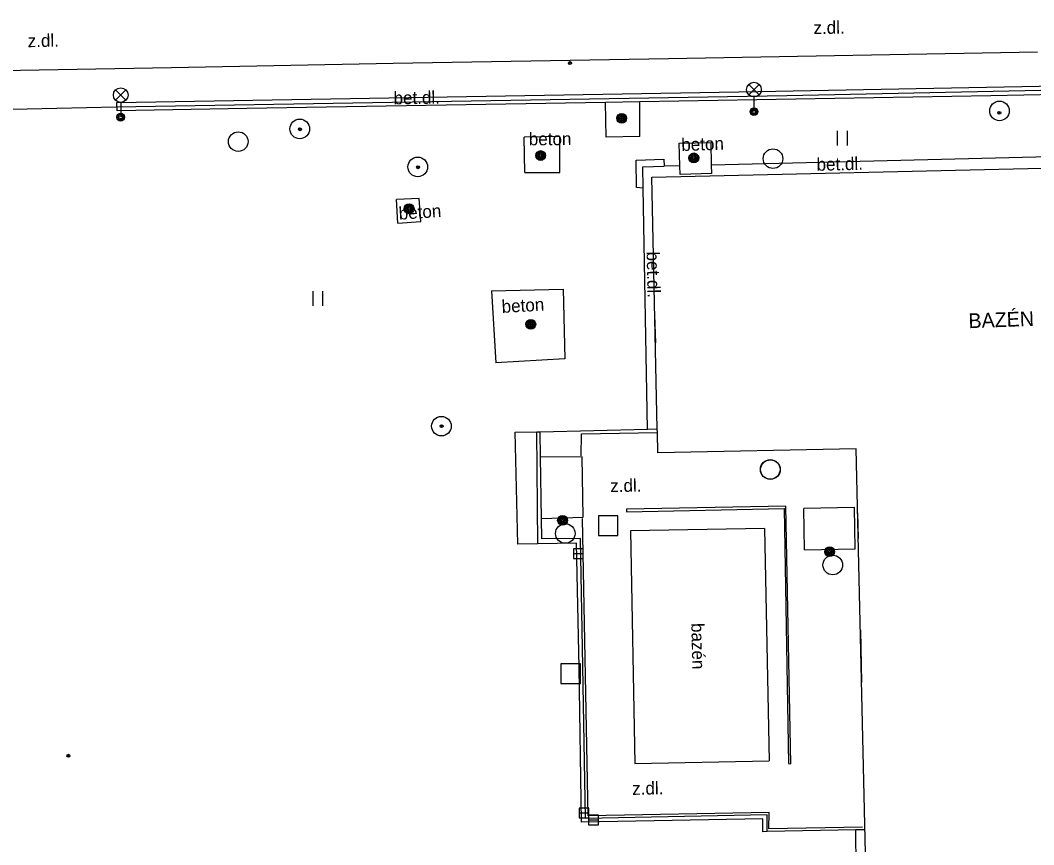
# Model space of a CAD drawing. Extents: x -641829 to -641525, y -1114855 to -1114359.
# Drawn here: x -641632.1 to -641580.3, y -1114713.1 to -1114671 of the extents above; entities that cross this region are included whole.
import ezdxf

# ---------------------------------------------------------------- set-up
doc = ezdxf.new("R2010")
doc.units = 0
for name, color, linetype in [('Vrstva 11', 7, 'Continuous'), ('Vrstva 20', 7, 'Continuous'), ('Vrstva 25', 7, 'Continuous'), ('Vrstva 26', 7, 'Continuous'), ('Vrstva 27', 7, 'Continuous'), ('Vrstva 33', 7, 'Continuous'), ('Vrstva 36', 7, 'Continuous'), ('Vrstva 40', 7, 'Continuous'), ('Vrstva 41', 7, 'Continuous'), ('Vrstva 5', 7, 'Continuous'), ('Vrstva 6', 7, 'Continuous'), ('Vrstva 7', 7, 'Continuous')]:
    doc.layers.add(name, color=color, linetype=linetype)

msp = doc.modelspace()

# ---------------------------------------------------------------- linework, layer by layer
at = {"layer": 'Vrstva 11'}
for p, q in [((-641613.03, -1114673.15), (-641598.98, -1114672.9)), ((-641598.98, -1114672.9), (-641580.14, -1114672.56)), ((-641633.01, -1114673.52), (-641624.34, -1114673.36)), ((-641624.34, -1114673.36), (-641613.03, -1114673.15)), ((-641594.4, -1114674.59), (-641569.41, -1114674.12)), ((-641561.56, -1114674.35), (-641582.52, -1114674.81)), ((-641627.12, -1114675.16), (-641594.4, -1114674.59)), ((-641627.11, -1114675.58), (-641627.12, -1114675.16)), ((-641620.5, -1114675.46), (-641627.11, -1114675.58)), ((-641602.16, -1114676.92), (-641602.19, -1114675.15)), ((-641600.44, -1114676.89), (-641600.44, -1114675.12)), ((-641604.52, -1114676.88), (-641606.34, -1114676.92)), ((-641606.3, -1114678.73), (-641606.34, -1114676.92)), ((-641604.51, -1114678.72), (-641604.52, -1114676.88)), ((-641600.44, -1114676.89), (-641602.16, -1114676.92)), ((-641598.43, -1114677.23), (-641596.8, -1114677.19)), ((-641600.62, -1114678.1), (-641599.21, -1114678.05)), ((-641600.61, -1114679.5), (-641600.62, -1114678.1)), ((-641599.21, -1114678.05), (-641599.2, -1114678.4)), ((-641579.53, -1114677.93), (-641596.77, -1114678.35)), ((-641600.28, -1114678.44), (-641599.2, -1114678.4)), ((-641600.27, -1114679.52), (-641600.28, -1114678.44)), ((-641598.39, -1114678.38), (-641599.2, -1114678.4)), ((-641606.3, -1114678.73), (-641604.51, -1114678.72)), ((-641596.76, -1114678.78), (-641598.38, -1114678.83)), ((-641600.27, -1114679.52), (-641600.61, -1114679.5)), ((-641600.05, -1114691.83), (-641600.27, -1114679.52)), ((-641611.69, -1114680.05), (-641612.85, -1114680.11)), ((-641612.79, -1114681.31), (-641612.85, -1114680.11)), ((-641611.61, -1114681.23), (-641611.69, -1114680.05)), ((-641612.79, -1114681.31), (-641611.61, -1114681.23)), ((-641608, -1114684.77), (-641604.35, -1114684.68)), ((-641608, -1114684.77), (-641607.79, -1114688.44)), ((-641604.35, -1114684.68), (-641604.26, -1114688.24)), ((-641604.26, -1114688.24), (-641607.79, -1114688.44)), ((-641606.79, -1114691.99), (-641605.7, -1114691.97)), ((-641606.67, -1114697.71), (-641606.79, -1114691.99)), ((-641605.64, -1114697.69), (-641605.7, -1114691.97)), ((-641605.7, -1114691.97), (-641605.53, -1114691.97)), ((-641605.5, -1114693.27), (-641605.53, -1114691.97)), ((-641603.38, -1114693.24), (-641605.5, -1114693.27)), ((-641605.45, -1114696.4), (-641605.5, -1114693.27)), ((-641603.32, -1114696.33), (-641603.38, -1114693.24)), ((-641592.99, -1114695.76), (-641601.11, -1114695.92)), ((-641601.11, -1114696.05), (-641593.07, -1114695.89)), ((-641601.11, -1114695.92), (-641601.11, -1114696.05)), ((-641593.07, -1114695.89), (-641592.84, -1114708.91)), ((-641592.73, -1114708.92), (-641592.99, -1114695.76)), ((-641589.48, -1114695.83), (-641592.06, -1114695.88)), ((-641592.03, -1114698), (-641592.06, -1114695.88)), ((-641589.44, -1114697.94), (-641589.48, -1114695.83)), ((-641605.45, -1114696.4), (-641603.32, -1114696.33)), ((-641605.43, -1114697.43), (-641605.45, -1114696.4)), ((-641594.08, -1114696.91), (-641600.92, -1114697.02)), ((-641600.92, -1114697.02), (-641600.69, -1114708.91)), ((-641594.08, -1114696.91), (-641593.84, -1114708.77)), ((-641605.64, -1114697.69), (-641606.67, -1114697.71)), ((-641603.67, -1114697.66), (-641605.64, -1114697.69)), ((-641603.46, -1114697.42), (-641605.43, -1114697.43)), ((-641603.54, -1114704.01), (-641603.67, -1114697.66)), ((-641603.34, -1114703.96), (-641603.46, -1114697.42)), ((-641592.03, -1114698), (-641589.44, -1114697.94)), ((-641603.41, -1114711.9), (-641603.54, -1114704.01)), ((-641603.21, -1114711.71), (-641603.34, -1114703.96)), ((-641600.69, -1114708.91), (-641593.84, -1114708.77)), ((-641592.84, -1114708.91), (-641592.73, -1114708.92)), ((-641594.16, -1114711.74), (-641603.41, -1114711.9)), ((-641593.94, -1114711.53), (-641603.21, -1114711.71)), ((-641594.15, -1114712.39), (-641594.16, -1114711.74)), ((-641593.93, -1114712.38), (-641593.94, -1114711.53)), ((-641593.93, -1114712.38), (-641594.15, -1114712.39)), ((-641589.42, -1114712.3), (-641593.93, -1114712.38)), ((-641588.95, -1114712.3), (-641589.42, -1114712.3)), ((-641589.32, -1114718.12), (-641589.42, -1114712.3))]:
    msp.add_line(p, q, dxfattribs=at)
for points in [[(-641582.52, -1114674.81), (-641600.44, -1114675.12), (-641602.19, -1114675.15), (-641620.5, -1114675.46)], [(-641598.38, -1114678.83), (-641598.39, -1114678.38), (-641598.43, -1114677.23)], [(-641596.76, -1114678.78), (-641596.77, -1114678.35), (-641596.8, -1114677.19)], [(-641605.53, -1114691.97), (-641600.05, -1114691.83), (-641599.55, -1114691.82)]]:
    msp.add_lwpolyline(points, dxfattribs=at)
at = {"layer": 'Vrstva 20'}
for centre, radius in [((-641604, -1114673.14), 0.075), ((-641604, -1114673.14), 0.0204), ((-641582.09, -1114675.68), 0.075), ((-641582.09, -1114675.68), 0.0204), ((-641617.78, -1114676.52), 0.075), ((-641617.78, -1114676.52), 0.0204), ((-641611.75, -1114678.46), 0.075), ((-641611.75, -1114678.46), 0.0204), ((-641610.55, -1114691.68), 0.075), ((-641610.55, -1114691.68), 0.0204), ((-641629.6, -1114708.51), 0.075), ((-641629.6, -1114708.51), 0.0204)]:
    msp.add_circle(centre, radius, dxfattribs=at)
at = {"layer": 'Vrstva 25'}
for centre, radius in [((-641601.36, -1114675.96), 0.25), ((-641601.36, -1114675.96), 0.2), ((-641601.36, -1114675.96), 0.15), ((-641601.36, -1114675.96), 0.1), ((-641601.36, -1114675.96), 0.05), ((-641605.5, -1114677.86), 0.25), ((-641605.5, -1114677.86), 0.2), ((-641605.5, -1114677.86), 0.15), ((-641605.5, -1114677.86), 0.1), ((-641605.5, -1114677.86), 0.05), ((-641597.68, -1114677.98), 0.25), ((-641597.68, -1114677.98), 0.2), ((-641597.68, -1114677.98), 0.15), ((-641597.68, -1114677.98), 0.1), ((-641597.68, -1114677.98), 0.05), ((-641612.21, -1114680.58), 0.25), ((-641612.21, -1114680.58), 0.2), ((-641612.21, -1114680.58), 0.15), ((-641612.21, -1114680.58), 0.1), ((-641612.21, -1114680.58), 0.05), ((-641606, -1114686.48), 0.25), ((-641606, -1114686.48), 0.2), ((-641606, -1114686.48), 0.15), ((-641606, -1114686.48), 0.1), ((-641606, -1114686.48), 0.05), ((-641604.38, -1114696.49), 0.25), ((-641604.38, -1114696.49), 0.2), ((-641604.38, -1114696.49), 0.15), ((-641604.38, -1114696.49), 0.1), ((-641604.38, -1114696.49), 0.05), ((-641590.75, -1114698.09), 0.25), ((-641590.75, -1114698.09), 0.2), ((-641590.75, -1114698.09), 0.15), ((-641590.75, -1114698.09), 0.1), ((-641590.75, -1114698.09), 0.05)]:
    msp.add_circle(centre, radius, dxfattribs=at)
at = {"layer": 'Vrstva 26'}
for points in [[(-641602.55, -1114697.26), (-641601.55, -1114697.26), (-641601.55, -1114696.26), (-641602.55, -1114696.26)], [(-641604.47, -1114704.82), (-641603.47, -1114704.82), (-641603.47, -1114703.82), (-641604.47, -1114703.82)]]:
    msp.add_lwpolyline(points, close=True, dxfattribs=at)
at = {"layer": 'Vrstva 27'}
for p, q in [((-641603.82, -1114698.19), (-641603.32, -1114698.19)), ((-641603.54, -1114711.43), (-641603.04, -1114711.43)), ((-641603.05, -1114711.79), (-641602.55, -1114711.79))]:
    msp.add_line(p, q, dxfattribs=at)
for points in [[(-641603.82, -1114698.44), (-641603.32, -1114698.44), (-641603.32, -1114697.94), (-641603.82, -1114697.94)], [(-641603.54, -1114711.68), (-641603.04, -1114711.68), (-641603.04, -1114711.18), (-641603.54, -1114711.18)], [(-641603.05, -1114712.04), (-641602.55, -1114712.04), (-641602.55, -1114711.54), (-641603.05, -1114711.54)]]:
    msp.add_lwpolyline(points, close=True, dxfattribs=at)
for centre in [(-641582.08, -1114675.58), (-641617.79, -1114676.5), (-641620.93, -1114677.15), (-641593.64, -1114678.02), (-641611.77, -1114678.44), (-641610.56, -1114691.68), (-641593.78, -1114693.89), (-641593.77, -1114693.9), (-641604.24, -1114697.16), (-641590.59, -1114698.77)]:
    msp.add_circle(centre, 0.5, dxfattribs=at)
at = {"layer": 'Vrstva 33'}
for p, q in [((-641627.195, -1114675.04), (-641626.665, -1114674.51)), ((-641627.195, -1114674.51), (-641626.665, -1114675.04)), ((-641594.875, -1114674.76), (-641594.345, -1114674.23)), ((-641594.875, -1114674.23), (-641594.345, -1114674.76)), ((-641594.61, -1114674.87), (-641594.61, -1114675.62)), ((-641626.93, -1114675.15), (-641626.93, -1114675.9))]:
    msp.add_line(p, q, dxfattribs=at)
for centre, radius in [((-641626.93, -1114674.775), 0.375), ((-641594.61, -1114674.495), 0.375), ((-641594.61, -1114675.62), 0.2), ((-641594.61, -1114675.62), 0.145), ((-641594.61, -1114675.62), 0.0876), ((-641626.93, -1114675.9), 0.2), ((-641626.93, -1114675.9), 0.145), ((-641626.93, -1114675.9), 0.0876)]:
    msp.add_circle(centre, radius, dxfattribs=at)
at = {"layer": 'Vrstva 36'}
for p, q in [((-641590.344, -1114677.343), (-641590.344, -1114676.593)), ((-641589.844, -1114677.343), (-641589.844, -1114676.593)), ((-641617.114, -1114685.533), (-641617.114, -1114684.783)), ((-641616.614, -1114685.533), (-641616.614, -1114684.783))]:
    msp.add_line(p, q, dxfattribs=at)
at = {"layer": 'Vrstva 5'}
for p, q in [((-641599.83, -1114678.97), (-641563.52, -1114678.12)), ((-641589.39, -1114692.83), (-641599.52, -1114693.05)), ((-641588.52, -1114730.89), (-641589.39, -1114692.83))]:
    msp.add_line(p, q, dxfattribs=at)
msp.add_lwpolyline([(-641599.52, -1114693.05), (-641599.54, -1114692), (-641599.55, -1114691.82), (-641599.83, -1114678.97)], dxfattribs=at)
at = {"layer": 'Vrstva 6'}
for p, q in [((-641599.68, -1114685.99), (-641599.64, -1114687.43)), ((-641589.32, -1114696.1), (-641589.29, -1114697.42)), ((-641589.18, -1114702.1), (-641589.12, -1114704.75))]:
    msp.add_line(p, q, dxfattribs=at)
at = {"layer": 'Vrstva 7'}
for p, q in [((-641592.94, -1114674.79), (-641569.31, -1114674.3)), ((-641627.16, -1114675.37), (-641592.94, -1114674.79)), ((-641633.85, -1114675.52), (-641627.16, -1114675.37)), ((-641603.43, -1114693.2), (-641603.42, -1114692.07)), ((-641603.42, -1114692.07), (-641599.54, -1114692)), ((-641603.07, -1114711.58), (-641603.36, -1114696.39)), ((-641593.83, -1114711.41), (-641603.07, -1114711.58)), ((-641593.85, -1114712.25), (-641593.83, -1114711.41)), ((-641589.08, -1114712.15), (-641593.85, -1114712.25))]:
    msp.add_line(p, q, dxfattribs=at)

# ---------------------------------------------------------------- texts
at = {"layer": 'Vrstva 40'}
for s, height, rotation, p in [('z.dl.', 0.6499, 1.0339, (-641591.57, -1114671.66)), ('z.dl.', 0.6499, 1.1559, (-641631.67, -1114672.33)), ('bet.dl.', 0.65, 0.9805, (-641613, -1114675.25)), ('beton', 0.65, 0.3201, (-641606.1, -1114677.34)), ('beton', 0.6499, 1.7689, (-641598.31, -1114677.63)), ('bet.dl.', 0.65, 1.341, (-641591.41, -1114678.64)), ('beton', 0.65, 3.8851, (-641612.72, -1114681.14)), ('bet.dl.', 0.65, 271.2608, (-641600.09, -1114682.77)), ('beton', 0.65, 3.2428, (-641607.47, -1114685.9)), ('z.dl.', 0.65, 1.1288, (-641601.94, -1114695.05)), ('bazén', 0.65, 271.3502, (-641597.81, -1114701.74)), ('z.dl.', 0.65, 1.1124, (-641600.82, -1114710.51))]:
    msp.add_text(s, height=height, rotation=rotation, dxfattribs=at).set_placement(p)
at = {"layer": 'Vrstva 41'}
msp.add_text('BAZÉN', height=0.75, rotation=2.1637, dxfattribs=at).set_placement((-641583.65, -1114686.68))

doc.saveas('drawing.dxf')
